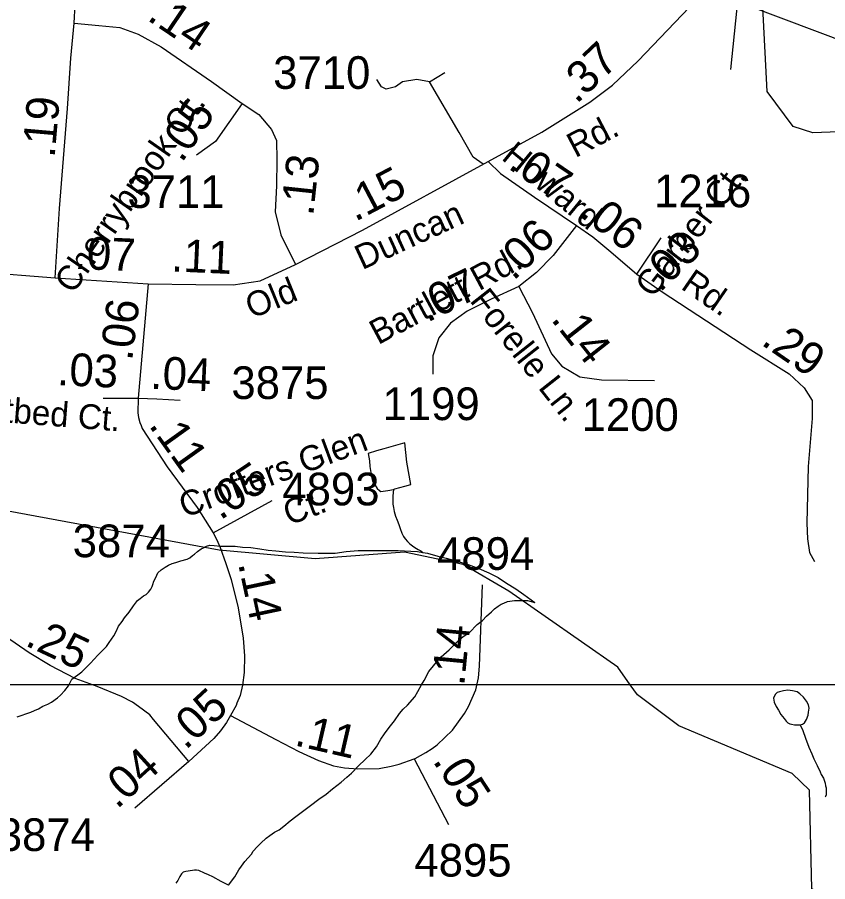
# Model space of a CAD drawing. Extents: x 2001466 to 2224147, y 644118 to 847247.
# Drawn here: x 2053637 to 2056739, y 657420 to 660729 of the extents above; entities that cross this region are included whole.
import ezdxf

# ---------------------------------------------------------------- set-up
doc = ezdxf.new("R2010")
doc.units = 0
for name, color, linetype in [('Exist Hydrographic Creek Single Shore', 7, 'Continuous'), ('Exist Hydrographic Misc Water Feature', 7, 'Continuous'), ('Exist Road Non-System Type 51', 7, 'Continuous'), ('Exist Road Non-System Type 51 Label', 7, 'Continuous'), ('Exist Road Secondary Mileage Hundredths English Label', 7, 'Continuous'), ('Exist Road Secondary Structure Standard Bridge CELL', 7, 'Continuous'), ('Exist Road Secondary Type 51 Attributed', 7, 'Continuous'), ('Exist Road Secondary Type 51 Label', 7, 'Continuous'), ('Exist Road Secondary Type 51 Number Label', 7, 'Continuous'), ('Exist Utilities Electrical Transmission Line', 7, 'Continuous'), ('Map Preparation Inset Cut Line', 7, 'Continuous')]:
    doc.layers.add(name, color=color, linetype=linetype)

msp = doc.modelspace()

# ---------------------------------------------------------------- linework, layer by layer
at = {"layer": 'Exist Hydrographic Creek Single Shore'}
for points in [[(2056889.6, 660304.2), (2056849.2, 660292.8), (2056682, 660286.3), (2056607.2, 660310.8), (2056507.1, 660444.1), (2056491.3, 660767.9)], [(2055519, 658531.7), (2055344.1, 658633.7), (2055119.1, 658680.9), (2054777.1, 658655), (2054410.1, 658688.8), (2053435, 658869.3), (2052801, 659177.4), (2052643.1, 659187.2), (2052393.2, 659143), (2052327.1, 659101.7), (2052285.1, 658977.9), (2052269.1, 658827.3), (2052128, 658518.5)], [(2055983.4, 658173.9), (2055936.1, 658241.1), (2055519, 658531.7)], [(2057696, 656745.4), (2057605, 656786.6), (2057329, 657103.9), (2056961.9, 657285.2), (2056746, 657345.4), (2056679, 657392.7), (2056669.9, 657770.2), (2056603.1, 657833.8), (2056169, 658016.5), (2056011.1, 658134.6), (2055983.4, 658173.9)]]:
    msp.add_lwpolyline(points, dxfattribs=at)
at = {"layer": 'Exist Hydrographic Misc Water Feature'}
for points in [[(2055077.1, 658921.4), (2055083, 658923.4), (2055121, 658933.5), (2055143.1, 658939.6), (2055129, 659025.5), (2055120.8, 659099.5), (2055040.8, 659077.3), (2055012.9, 659069.3), (2054980.9, 659059.2), (2054985, 659031.2), (2054986.9, 659009.3), (2054988.9, 658993.3), (2054993, 658971.3), (2054997.1, 658953.3), (2055005.1, 658941.3), (2055011.1, 658931.3), (2055015.2, 658925.3), (2055023.2, 658917.3), (2055029.1, 658913.3), (2055047.2, 658915.4), (2055055.2, 658917.4), (2055077.1, 658921.4)], [(2055077.1, 658921.4), (2055075.2, 658897.4), (2055075.2, 658883.5), (2055075.2, 658865.5), (2055077.1, 658851.5), (2055079.3, 658837.4), (2055085.3, 658819.4), (2055091.2, 658803.5), (2055097.4, 658787.5), (2055103.3, 658771.5), (2055109.5, 658753.5), (2055115.4, 658741.6), (2055121.4, 658731.6), (2055131.4, 658721.6), (2055139.4, 658713.6), (2055149.5, 658705.6), (2055159.5, 658699.6), (2055171.6, 658691.6), (2055181.5, 658685.7), (2055189.5, 658679.7)], [(2053637, 658050.9), (2053688.9, 658069), (2053702.8, 658075), (2053718.8, 658081), (2053735, 658091.1), (2053754.9, 658099.1), (2053768.9, 658107.2), (2053790.8, 658123.2), (2053802.9, 658133.2), (2053818.9, 658151.2), (2053832.8, 658169.2), (2053846.8, 658195.3), (2053868.7, 658211.3), (2053884.7, 658223.3), (2053896.6, 658235.3), (2053916.5, 658255.3), (2053932.5, 658273.4), (2053944.6, 658285.4), (2053956.5, 658297.5), (2053978.4, 658319.5), (2053988.5, 658335.5), (2054006.3, 658361.5), (2054016.4, 658377.5), (2054024.4, 658397.5), (2054038.3, 658415.6), (2054048.1, 658429.6), (2054066.2, 658451.6), (2054082.2, 658475.7), (2054090, 658485.7), (2054098, 658495.6), (2054108, 658503.6), (2054120.1, 658513.7), (2054130.2, 658519.7), (2054140, 658527.7), (2054148, 658539.7), (2054153.9, 658549.8), (2054156, 658557.8), (2054159.9, 658569.8), (2054167.9, 658583.8), (2054175.9, 658601.8), (2054187.8, 658613.8), (2054203.8, 658623.9), (2054215.9, 658631.9), (2054229.8, 658637.9), (2054243.8, 658641.9), (2054251.8, 658643.9), (2054263.9, 658648), (2054287.8, 658654), (2054297.9, 658660), (2054307.7, 658668), (2054315.7, 658674), (2054327.6, 658684), (2054341.8, 658694.1), (2054349.8, 658698.1), (2054361.7, 658704.1), (2054373.8, 658708.2)], [(2054373.8, 658708.2), (2054391.6, 658706.2), (2054415.6, 658704.2), (2054443.7, 658704.3), (2054471.8, 658704.3), (2054499.7, 658700.3), (2054531.7, 658698.4), (2054565.7, 658694.5), (2054597.7, 658688.6), (2054627.6, 658686.6), (2054663.7, 658682.7), (2054697.7, 658680.8), (2054731.8, 658678.8), (2054789.6, 658676.9), (2054825.5, 658677), (2054853.6, 658677.1), (2054895.6, 658683.1), (2054941.6, 658687.3), (2054997.5, 658687.3), (2055049.6, 658687.4), (2055095.5, 658687.5), (2055143.5, 658685.6), (2055169.6, 658683.6), (2055189.5, 658679.7)], [(2055189.5, 658679.7), (2055207.5, 658677.7), (2055247.5, 658665.8), (2055279.5, 658657.9), (2055307.6, 658649.9), (2055363.5, 658634), (2055403.5, 658618.1), (2055441.7, 658602.2), (2055477.8, 658584.3), (2055509.8, 658562.3), (2055545.6, 658540.4), (2055575.8, 658518.5), (2055617.8, 658488.5)], [(2054445.9, 657406.6), (2054469.9, 657438.6), (2054485.9, 657464.6), (2054496, 657478.6), (2054507.9, 657496.6), (2054533.7, 657524.7), (2054539.9, 657536.7), (2054555.8, 657552.8), (2054569.6, 657566.8), (2054589.7, 657586.8), (2054603.6, 657596.8), (2054621.7, 657608.8), (2054639.5, 657618.9), (2054657.6, 657632.9), (2054681.5, 657652.9), (2054703.5, 657669), (2054729.3, 657689), (2054759.5, 657711.1), (2054791.2, 657735.1), (2054819.3, 657755.2), (2054843.3, 657775.2), (2054877.2, 657801.2), (2054899.1, 657819.3), (2054917.2, 657835.4), (2054943, 657863.4), (2054969, 657887.5), (2054991, 657907.5), (2055012.9, 657935.5), (2055028.9, 657965.5), (2055042.8, 657985.6), (2055060.7, 658009.6), (2055080.8, 658035.6), (2055100.7, 658063.7), (2055114.6, 658079.7), (2055130.6, 658095.7), (2055158.5, 658127.7), (2055170.6, 658147.8), (2055184.3, 658173.8), (2055194.4, 658189.8), (2055212.4, 658223.8), (2055230.3, 658245.9), (2055242.4, 658259.9), (2055260.2, 658279.9), (2055290.1, 658307.9), (2055328.1, 658346), (2055344.1, 658358.1), (2055368.1, 658374.1), (2055398, 658404.1), (2055417.9, 658420.2), (2055433.9, 658436.2), (2055451.9, 658452.2), (2055464, 658464.3), (2055477.8, 658474.3), (2055489.9, 658482.3), (2055499.7, 658486.3), (2055513.9, 658492.3), (2055539.9, 658496.4), (2055561.8, 658496.5), (2055589.7, 658496.5), (2055617.8, 658488.5)], [(2056634.5, 658020.5), (2056642.5, 658022.5), (2056650.5, 658028.5), (2056658.5, 658040.6), (2056664.4, 658056.6), (2056666.4, 658068.6), (2056668.3, 658084.6), (2056666.2, 658096.6), (2056658.2, 658110.6), (2056646.4, 658126.6), (2056632.2, 658138.6), (2056622.4, 658146.5), (2056604.1, 658150.5), (2056586.1, 658152.4), (2056570.3, 658150.4), (2056554.3, 658146.3), (2056546.3, 658144.3), (2056538.3, 658136.3), (2056532.3, 658122.4), (2056534.2, 658106.4), (2056542.2, 658090.4), (2056550.4, 658076.4), (2056560.4, 658060.4), (2056572.3, 658044.4), (2056580.3, 658034.4), (2056586.5, 658028.5), (2056594.5, 658024.5), (2056600.4, 658022.5), (2056612.3, 658020.5), (2056624.4, 658020.5), (2056634.5, 658020.5)], [(2056634.5, 658020.5), (2056644.5, 657998.6), (2056654.6, 657968.6), (2056666.7, 657934.6), (2056678.5, 657908.7), (2056686.5, 657890.7), (2056698.8, 657864.7), (2056710.7, 657840.7), (2056714.8, 657830.7), (2056722.8, 657816.7), (2056726.7, 657804.7), (2056729, 657796.7), (2056730.8, 657786.8), (2056732.9, 657778.8), (2056732.9, 657764.8), (2056732.9, 657752.8), (2056730.3, 657746.3), (2056729, 657742.8)], [(2054445.9, 657406.6), (2054418.1, 657420.5), (2054386.1, 657438.5), (2054369.9, 657446.3), (2054353.9, 657452.3), (2054331.9, 657462.3), (2054323.9, 657464.3), (2054315.9, 657464.3), (2054291.9, 657460.2), (2054281.9, 657458.2), (2054271.9, 657456.2), (2054266.1, 657450.2), (2054260, 657440.2), (2054252, 657424.2), (2054244, 657414.2)]]:
    msp.add_lwpolyline(points, dxfattribs=at)
at = {"layer": 'Exist Road Non-System Type 51'}
msp.add_line((2055215.6, 660481), (2055274.1, 660517), dxfattribs=at)
for points in [[(2055215.6, 660481), (2055166.1, 660490), (2055112.1, 660481), (2055085.1, 660463), (2055049.1, 660454), (2055031.2, 660463), (2055013.2, 660490)], [(2055420.1, 660166.1), (2055382, 660193), (2055328.1, 660287.5), (2055215.6, 660481)]]:
    msp.add_lwpolyline(points, dxfattribs=at)
at = {"layer": 'Exist Road Secondary Structure Standard Bridge CELL'}
msp.add_line((2056368.9, 660528.3), (2056396.2, 660802.9), dxfattribs=at)
at = {"layer": 'Exist Road Secondary Type 51 Attributed'}
for points in [[(2055439.6, 660176.7), (2055645.5, 660288.7), (2055828.6, 660403.8), (2055916.2, 660469.3), (2056014.4, 660562.3), (2056323.2, 660885.7), (2056545.2, 661103.3)], [(2053855.3, 660705.9), (2053862.6, 660850.7), (2053880.1, 660944.7), (2053922.3, 661015.4)], [(2053782.4, 659731), (2053798.8, 659996.1), (2053829.9, 660379.6), (2053842.6, 660571.8), (2053855.3, 660705.9)], [(2053855.3, 660705.9), (2053949.2, 660697.5), (2054030.5, 660689), (2054100.1, 660663.7), (2054187.7, 660615.1), (2054381.4, 660483.1), (2054498.1, 660398.6)], [(2054498.1, 660398.6), (2054396.2, 660252.8), (2054323.4, 660201)], [(2054498.1, 660398.6), (2054561.4, 660356.3), (2054610, 660299.3), (2054629, 660257), (2054631.1, 660183.1), (2054629, 660083.8), (2054624.7, 659984.5), (2054645.9, 659895.8), (2054702.3, 659781.7)], [(2054702.3, 659781.7), (2054958.8, 659913.7), (2055439.6, 660176.7)], [(2055439.6, 660176.7), (2055487.1, 660130.3), (2055617, 660040.5), (2055777.9, 659931.7)], [(2055777.9, 659931.7), (2055688.2, 659816.5), (2055624.9, 659752.1), (2055557.3, 659698.2)], [(2055777.9, 659931.7), (2055840.2, 659888.4), (2055908.8, 659831.3), (2056009.1, 659745.8)], [(2056009.1, 659745.8), (2056102.5, 659884.1)], [(2053164.4, 659780.6), (2053491.6, 659754.2), (2053782.4, 659731)], [(2054138.7, 659707.7), (2054320.7, 659705.6), (2054463.2, 659704.6), (2054566.7, 659719.4), (2054702.3, 659781.7)], [(2053782.4, 659731), (2054138.7, 659707.7)], [(2056009.1, 659745.8), (2056105.2, 659677.1), (2056445.6, 659455.3), (2056591.2, 659363.4), (2056649.3, 659310.6), (2056680.4, 659262), (2056680.4, 659192.3), (2056664.6, 659008.5), (2056659.9, 658791.9), (2056662.3, 658731.8), (2056669.3, 658680.4), (2056688.4, 658645.9)], [(2054138.7, 659707.7), (2054100.1, 659270.9)], [(2055557.3, 659698.2), (2055451.2, 659649.7), (2055359.4, 659603.2), (2055295, 659557.8), (2055250.7, 659501.8), (2055227.5, 659432.1), (2055228.5, 659362.3)], [(2055557.3, 659698.2), (2055609, 659597.9), (2055682.4, 659440.5), (2055721.5, 659393), (2055791.1, 659352.8), (2055873.5, 659341.2), (2056076.1, 659338)], [(2053965.6, 659270.4), (2054100.1, 659270.9)], [(2054100.1, 659270.9), (2054099.4, 659214.2), (2054101.5, 659196.7), (2054106.9, 659177.4), (2054111.2, 659166), (2054116, 659154.2), (2054211, 659007.4), (2054326, 658851.9), (2054387, 658755.3)], [(2054100.1, 659270.9), (2054171.6, 659268.3), (2054260.6, 659263.2)], [(2054387, 658755.3), (2054613.4, 658879)], [(2054387, 658755.3), (2054400.1, 658730.8), (2054413.6, 658699.3), (2054436.1, 658638.2), (2054455.9, 658576.2), (2054482.2, 658467.7), (2054502.2, 658352.1), (2054507, 658284.1), (2054505.8, 658220.9), (2054499.8, 658171.9), (2054490, 658133.1), (2054478.1, 658102.9), (2054474.8, 658094), (2054453.2, 658056.2)], [(2054293.5, 657880.2), (2054158.6, 658041), (2054145.3, 658057.9), (2054101.7, 658090.6), (2054078.1, 658106.4), (2054035.8, 658129.1), (2053943.6, 658166.8), (2053859.2, 658198.2), (2053763.8, 658247.8), (2053683.5, 658295.8), (2053554.3, 658384.2), (2053452.9, 658456.7), (2053396.1, 658527.7), (2053365.5, 658591.5), (2053345, 658652.5)], [(2055156.1, 657890.2), (2055160.9, 657891.9), (2055201.3, 657914.3), (2055225.3, 657929.1), (2055244.1, 657944), (2055302.9, 657999.7), (2055348.8, 658063.6), (2055364.1, 658090), (2055391.9, 658153.9), (2055403.1, 658200.1), (2055406.9, 658244.8), (2055418.3, 658556.2)], [(2054453.2, 658056.2), (2054438.3, 658028.8), (2054415.7, 657997.2), (2054390.3, 657967.3), (2054293.5, 657880.2)], [(2054453.2, 658056.2), (2054626.7, 657964.2), (2054715, 657917.7), (2054790.9, 657883.4), (2054847.3, 657863.8), (2054890.4, 657855.2), (2054940.4, 657851.6), (2055022.6, 657853.7), (2055068.2, 657861.5), (2055099.7, 657869.4), (2055156.1, 657890.2)], [(2054293.5, 657880.2), (2054087.3, 657700.9)], [(2055156.1, 657890.2), (2055288.5, 657639)]]:
    msp.add_lwpolyline(points, dxfattribs=at)
at = {"layer": 'Exist Utilities Electrical Transmission Line'}
msp.add_lwpolyline([(2063583.7, 657590.1), (2059873.3, 658420.5), (2058009.5, 660180.5), (2056432.8, 660774), (2050997.3, 663369.7), (2049560.3, 664054.6)], dxfattribs=at)
at = {"layer": 'Map Preparation Inset Cut Line'}
for p, q in [((2055983.4, 658173.9), (2052640.1, 658173.9)), ((2057121.4, 658173.9), (2055983.4, 658173.9))]:
    msp.add_line(p, q, dxfattribs=at)

# ---------------------------------------------------------------- texts
at = {"layer": 'Exist Road Non-System Type 51 Label'}
for s, rotation, p in [('Plantbed Ct.', 355.4566, (2053331, 659198.8)), ('Crofters Glen', 20.3468, (2054278.1, 658811.8)), ('Ct.', 20.3468, (2054677, 658782.6))]:
    msp.add_text(s, height=95, rotation=rotation, dxfattribs=at).set_placement(p)
at = {"layer": 'Exist Road Secondary Mileage Hundredths English Label'}
for s, rotation, p in [('.14', 325.8766, (2054130.3, 660720.9)), ('.37', 43.438, (2055777.6, 660394.1)), ('.19', 84.9747, (2053780, 660188.8)), ('.05', 55.1846, (2054266.7, 660168.6)), ('.13', 83.8865, (2054769.8, 659965.8)), ('.07', 325.8376, (2055511.5, 660152.5)), ('.15', 27.7088, (2054930.6, 659944.6)), ('.06', 322.2704, (2055785.6, 659969.8)), ('.06', 43.849, (2055536.4, 659717.4)), ('.07', 357.4511, (2053855, 659766.2)), ('.03', 43.849, (2056096.4, 659672.2)), ('.11', 357.4511, (2054225.1, 659756.2)), ('.07', 26.0307, (2055206.1, 659558.9)), ('.06', 82.744, (2054076.7, 659411.3)), ('.14', 308.2469, (2055677.3, 659571.9)), ('.29', 325.428, (2056480.4, 659478.2)), ('.03', 357.4511, (2053788.4, 659320.6)), ('.04', 357.4511, (2054145.1, 659306.9)), ('.11', 305.5952, (2054138.1, 659166.5)), ('.05', 33.963, (2054414.1, 658801.2)), ('.14', 282.053, (2054482.3, 658637.3)), ('.25', 334.8964, (2053663, 658325.7)), ('.14', 84.4698, (2055347.9, 658167.2)), ('.05', 42.7777, (2054281.6, 657921.5)), ('.11', 347.0119, (2054694.7, 657942.4)), ('.04', 42.2819, (2054019.1, 657694.9)), ('.05', 303.1712, (2055225.3, 657882))]:
    msp.add_text(s, height=125, rotation=rotation, dxfattribs=at).set_placement(p)
at = {"layer": 'Exist Road Secondary Type 51 Label'}
for s, rotation, p in [('Cherrybrook Ct.', 55.1846, (2053850.9, 659665.8)), ('Rd.', 27.6463, (2055773.4, 660188.8)), ('Howard', 320.6936, (2055486.7, 660186.7)), ('Garber Ct.', 52.3407, (2056070.1, 659650.2)), ('Duncan', 24.7237, (2054957.5, 659760.1)), ('Bartlett Rd.', 28.1415, (2055018.6, 659473.3)), ('Rd.', 325.428, (2056173.2, 659692)), ('Old', 22.037, (2054534.6, 659573.7)), ('Forelle Ln.', 308.2469, (2055366.2, 659643.2))]:
    msp.add_text(s, height=95, rotation=rotation, dxfattribs=at).set_placement(p)
at = {"layer": 'Exist Road Secondary Type 51 Number Label'}
for s, p in [('3710', (2054616.9, 660454.5)), ('3711', (2054058.9, 659998.7)), ('1216', (2056074.7, 660001.4)), ('3875', (2054456.9, 659267.4)), ('1199', (2055035.4, 659186.7)), ('1200', (2055797.5, 659145.2)), ('4893', (2054652, 658860.3)), ('3874', (2053849.5, 658661.9)), ('4894', (2055244.5, 658613.2)), ('3874', (2053562.8, 657537.2)), ('4895', (2055157.4, 657439.5))]:
    msp.add_text(s, height=125, dxfattribs=at).set_placement(p)

doc.saveas('drawing.dxf')
